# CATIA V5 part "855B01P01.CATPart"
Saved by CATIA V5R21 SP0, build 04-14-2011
Part number: 855B01P01
Bounding box of the stored display mesh (mm): x -76.5 to 76.5, y -25.54 to 25.54, z -56.557 to 6.5
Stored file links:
  C:\Users\ALI OZGUN\Desktop\alhan\855B01P01.CATPart
  Copy (1) of 845B01P21.CATPart
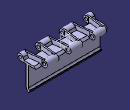
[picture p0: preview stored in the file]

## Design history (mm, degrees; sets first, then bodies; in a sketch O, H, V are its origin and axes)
Body1 (main body)
  Sketch1 on yz-plane, origin (0, 0, 0), H (0, 1, 0), V (0, 0, 1)
    construction line L1 (-19.05, 0) -> (19.05, 0)
    point P1 (-19.05, 0)
    point P2 (19.05, 0)
    line L2 (-19.05, 6.5) -> (19.05, 6.5)
    line L3 (19.05, -6.5) -> (-19.05, -6.5)
    arc A1 centre (19.05, 0) radius 6.5 from (19.05, 6.5) to (19.05, -6.5) cw
    arc A2 centre (-19.05, 0) radius 6.5 from (-19.05, -6.5) to (-19.05, 6.5) cw
    circle A3 centre (19.05, 0) radius 3.25
    circle A4 centre (-19.05, 0) radius 3.25
    distance L1 L2 = 6.5
    length L1 = 38.1
    distance P2 V = 19.05
    radius A3 = 3.25
    radius A4 = 3.25
    coincidence: P1 H
    horizontal: L1 H
    tangency: A1 L2, A2 L2, A1 L3, A2 L3
  Pad1: profile Sketch1, direction (1, 0, 0), length 76.5, mirrored extent
  Sketch2 on face of Pad1 from Sketch1.L2, origin (0, 0, 6.5), H (1, 0, 0), V (0, 1, 0)
    line L1 (38, -14) -> (64, -14)
    line L2 (64, -14) -> (64, -36.0786)
    line L3 (64, -36.0786) -> (38, -36.0786)
    line L4 (38, -36.0786) -> (38, -14)
    line L5 (-13, -14) -> (13, -14)
    line L6 (13, -14) -> (13, -36.0786)
    line L7 (13, -36.0786) -> (-13, -36.0786)
    line L8 (-13, -36.0786) -> (-13, -14)
    point P7 (13, -36.0786)
    line L9 (-64, -14) -> (-38, -14)
    line L10 (-38, -14) -> (-38, -32.269)
    line L11 (-38, -32.269) -> (-64, -32.269)
    line L12 (-64, -32.269) -> (-64, -14)
    line L13 (85.7823, 31.3847) -> (63.5, 31.3847)
    line L14 (63.5, 31.3847) -> (63.5, 14)
    line L15 (63.5, 14) -> (85.7823, 14)
    line L16 (85.7823, 14) -> (85.7823, 31.3847)
    point P17 (12.5, 31.3847)
    line L17 (12.5, 31.3847) -> (38.5, 31.3847)
    line L18 (38.5, 31.3847) -> (38.5, 14)
    line L19 (38.5, 14) -> (12.5, 14)
    line L20 (12.5, 14) -> (12.5, 31.3847)
    point P19 (38.5, 14)
    line L21 (-38.5, 32.0801) -> (-12.5, 32.0801)
    line L22 (-12.5, 32.0801) -> (-12.5, 14)
    line L23 (-12.5, 14) -> (-38.5, 14)
    line L24 (-38.5, 14) -> (-38.5, 32.0801)
    point P23 (-12.5, 14)
    line L25 (-81.4786, 33.8185) -> (-63.5, 33.8185)
    line L26 (-63.5, 33.8185) -> (-63.5, 14)
    line L27 (-63.5, 14) -> (-81.4786, 14)
    line L28 (-81.4786, 14) -> (-81.4786, 33.8185)
    point P27 (-63.5, 14)
    reference projected line E1 (76.5, 19.05) -> (76.5, -19.05) from edge [face of Pad1 from Sketch1.L2 | end face of Pad1]
    reference projected line E2 (-76.5, 19.05) -> (-76.5, -19.05) from edge [start face of Pad1 | face of Pad1 from Sketch1.L2]
    reference projected line E3 (-76.5, 19.05) -> (-76.5, -19.05) from edge [start face of Pad1 | face of Pad1 from Sketch1.L2]
    reference projected line E4 (76.5, 19.05) -> (76.5, -19.05) from edge [face of Pad1 from Sketch1.L2 | end face of Pad1]
    distance L14 E1 = 13
    distance L26 E2 = 13
    distance L12 E3 = 12.5
    distance L2 E4 = 12.5
    distance L23 L5 = 28
    distance L5 H = 14
    distance L4 L2 = 26
    distance L12 L10 = 26
    distance L10 L8 = 25
    distance L6 L4 = 25
    distance L24 L26 = 25
    distance L18 L14 = 25
    distance L26 L22 = 51
    distance L20 L18 = 26
    horizontal: L1 H, L3 H, L5 H, L7 H, L9 H, L11 H, L13 H, L15 H, L17 H, L19 H, L21 H, L23 H, L25 H, L27 H
    vertical: L2 V, L4 V, L6 V, L8 V, L10 V, L12 V, L14 V, L16 V, L18 V, L20 V, L22 V, L24 V, L26 V, L28 V
    coincidence: P7 L3, P17 L13, P19 L15, P23 L15, P27 L15, L1 L5, L9 L5
  Pocket1: profile Sketch2, direction (0, 0, -1), length 53.5
  Sketch3 on end face of Pad1, origin (76.5, 0, 0), H (0, 1, 0), V (0, 0, 1)
    projected arc E1 centre (19.05, 0) radius 6.5 from (19.05, -6.5) to (19.05, 6.5) ccw from edge [face of Pocket1 from Sketch2.L14 | face of Pad1 from Sketch1.A1]
    projected arc E2 centre (19.05, 0) radius 6.5 from (19.05, -6.5) to (13.0358, 2.4657) ccw from edge [face of Pocket1 from Sketch2.L14 | face of Pad1 from Sketch1.A1]
    point P1 (19.05, -6.5)
    projected arc E3 centre (-19.05, 0) radius 6.5 from (-19.05, 6.5) to (-19.05, -6.5) ccw from edge [face of Pad1 from Sketch1.A2 | end face of Pad1]
    projected arc E4 centre (-19.05, 0) radius 6.5 from (-13.0358, 2.4657) to (-19.05, -6.5) ccw from edge [face of Pad1 from Sketch1.A2 | end face of Pad1]
    point P4 (-19.05, -6.5)
    projected line E5 (-19.05, -6.5) -> (14, -6.5) from edge [face of Pad1 from Sketch1.L3 | end face of Pad1]
    point P5 (-19.05, -6.5)
    projected line E6 (19.05, -6.5) -> (14, -6.5) from edge [face of Pocket1 from Sketch2.L14 | face of Pad1 from Sketch1.L3]
    point P7 (19.05, -6.5)
    line L1 (-13.0358, 2.4657) -> (-11, -2.5)
    line L2 (-11, -2.5) -> (11, -2.5)
    point P10 (11, -2.5)
    line L3 (11, -2.5) -> (13.0358, 2.4657)
    distance L2 E5 = 4
    length L2 = 22
    distance P10 V = 11
    horizontal: L2 H
    tangency: L3 E1, L1 E3
    coincidence: P1 P7, P4 P5
  Pocket2: profile Sketch3, direction (-1, 0, 0), length 172.5, outer side
  Sketch4 on face of Pocket2 from Sketch3.L2, origin (0, 0, -2.5), H (1, 0, 0), V (0, 1, 0)
    projected line E1 (38, -14) -> (38, -25.55) from edge [face of Pocket2 | face of Pocket1 from Sketch2.L4]
    projected line E2 (38, -14) -> (38, -19.05) from edge [face of Pocket2 | face of Pocket1 from Sketch2.L4]
    point P1 (38, -14)
    point P2 (38, -25.55)
    projected line E3 (13, -25.55) -> (13, -14) from edge [face of Pocket2 | face of Pocket1 from Sketch2.L6]
    projected line E4 (13, -19.05) -> (13, -14) from edge [face of Pocket2 | face of Pocket1 from Sketch2.L6]
    point P3 (13, -25.55)
    point P4 (13, -14)
    projected line E5 (64, -25.55) -> (64, -14) from edge [face of Pocket2 | face of Pocket1 from Sketch2.L2]
    projected line E6 (64, -19.05) -> (64, -14) from edge [face of Pocket2 | face of Pocket1 from Sketch2.L2]
    point P5 (64, -25.55)
    point P6 (64, -14)
    projected line E7 (38.5, 14) -> (38.5, 25.55) from edge [face of Pocket2 | face of Pocket1 from Sketch2.L18]
    projected line E8 (38.5, 14) -> (38.5, 19.05) from edge [face of Pocket2 | face of Pocket1 from Sketch2.L18]
    point P7 (38.5, 14)
    point P8 (38.5, 25.55)
    projected line E9 (63.5, 14) -> (63.5, 25.55) from edge [face of Pocket1 from Sketch2.L14 | face of Pocket2]
    projected line E10 (63.5, 14) -> (63.5, 19.05) from edge [face of Pocket1 from Sketch2.L14 | face of Pocket2]
    point P9 (63.5, 14)
    point P10 (63.5, 25.55)
    projected line E11 (12.5, 25.55) -> (12.5, 14) from edge [face of Pocket2 | face of Pocket1 from Sketch2.L20]
    projected line E12 (12.5, 19.05) -> (12.5, 14) from edge [face of Pocket2 | face of Pocket1 from Sketch2.L20]
    point P11 (12.5, 25.55)
    point P12 (12.5, 14)
    offset line E13 (9.5, 25.55) -> (9.5, 14) from edge [face of Pocket2 | face of Pocket1 from Sketch2.L20]
    offset line E14 (9.5, 19.05) -> (9.5, 14) from edge [face of Pocket2 | face of Pocket1 from Sketch2.L20]
    point P13 (9.5, 25.55)
    point P14 (9.5, 14)
    offset line E15 (16, -25.55) -> (16, -14) from edge [face of Pocket2 | face of Pocket1 from Sketch2.L6]
    offset line E16 (16, -19.05) -> (16, -14) from edge [face of Pocket2 | face of Pocket1 from Sketch2.L6]
    point P15 (16, -25.55)
    point P16 (16, -14)
    offset line E17 (35, -14) -> (35, -25.55) from edge [face of Pocket2 | face of Pocket1 from Sketch2.L4]
    offset line E18 (35, -14) -> (35, -19.05) from edge [face of Pocket2 | face of Pocket1 from Sketch2.L4]
    point P17 (35, -14)
    point P18 (35, -25.55)
    offset line E19 (41.5, 14) -> (41.5, 25.55) from edge [face of Pocket2 | face of Pocket1 from Sketch2.L18]
    offset line E20 (41.5, 14) -> (41.5, 19.05) from edge [face of Pocket2 | face of Pocket1 from Sketch2.L18]
    point P19 (41.5, 14)
    point P20 (41.5, 25.55)
    offset line E21 (60.5, 14) -> (60.5, 25.55) from edge [face of Pocket1 from Sketch2.L14 | face of Pocket2]
    offset line E22 (60.5, 14) -> (60.5, 19.05) from edge [face of Pocket1 from Sketch2.L14 | face of Pocket2]
    point P21 (60.5, 14)
    point P22 (60.5, 25.55)
    offset line E23 (67, -25.55) -> (67, -14) from edge [face of Pocket2 | face of Pocket1 from Sketch2.L2]
    offset line E24 (67, -19.05) -> (67, -14) from edge [face of Pocket2 | face of Pocket1 from Sketch2.L2]
    point P23 (67, -25.55)
    point P24 (67, -14)
    line L1 (13, -14) -> (9.5, 14)
    line L2 (16, -14) -> (12.5, 14)
    line L3 (35, -14) -> (38.5, 14)
    line L4 (38, -14) -> (41.5, 14)
    line L5 (64, -14) -> (60.5, 14)
    line L6 (67, -14) -> (63.5, 14)
    projected line E25 through (0, -19.05) direction (1, 0) from axis of face of Pocket2
    projected line E26 (13, -19.05) -> (16, -19.05) from axis of face of Pocket2
    projected line E27 (64, -19.05) -> (67, -19.05) from axis of face of Pocket2
    projected line E28 (35, -19.05) -> (38, -19.05) from axis of face of Pocket2
    point P25 (-10000000, -19.05)
    point P26 (10000000, -19.05)
    point P27 (67, -19.05)
    point P28 (38, -19.05)
    point P29 (64, -19.05)
    point P30 (64, -19.05)
    point P31 (38, -19.05)
    point P32 (35, -19.05)
    point P33 (16, -19.05)
    point P34 (35, -19.05)
    point P35 (16, -19.05)
    point P36 (13, -19.05)
    point P37 (13, -19.05)
    projected line E29 through (0, 19.05) direction (1, 0) from axis of face of Pocket2
    projected line E30 (9.5, 19.05) -> (12.5, 19.05) from axis of face of Pocket2
    projected line E31 (38.5, 19.05) -> (41.5, 19.05) from axis of face of Pocket2
    projected line E32 (60.5, 19.05) -> (63.5, 19.05) from axis of face of Pocket2
    point P38 (-10000000, 19.05)
    point P39 (10000000, 19.05)
    point P40 (63.5, 19.05)
    point P41 (9.5, 19.05)
    point P42 (9.5, 19.05)
    point P43 (12.5, 19.05)
    point P44 (12.5, 19.05)
    point P45 (38.5, 19.05)
    point P46 (38.5, 19.05)
    point P47 (41.5, 19.05)
    point P48 (60.5, 19.05)
    point P49 (41.5, 19.05)
    point P50 (60.5, 19.05)
    point P51 (-10000000, -19.05)
    point P52 (10000000, -19.05)
    point P53 (-10000000, 19.05)
    point P54 (10000000, 19.05)
    construction line L7 through (0, -19.05) direction (-1, 0)
    construction line L8 through (0, 19.05) direction (-1, 0)
    point P55 (-10000000, -19.05)
    point P56 (10000000, -19.05)
    point P57 (-16, -19.05)
    point P58 (-13, -19.05)
    point P59 (-67, -19.05)
    point P60 (-64, -19.05)
    point P61 (-38, -19.05)
    point P62 (-35, -19.05)
    point P63 (-38, -25.55)
    point P64 (-38, -14)
    point P65 (-38, -19.05)
    point P66 (-13, -14)
    point P67 (-13, -25.55)
    point P68 (-13, -19.05)
    point P69 (-64, -14)
    point P70 (-64, -25.55)
    point P71 (-64, -19.05)
    point P72 (-38.5, 25.55)
    point P73 (-38.5, 14)
    point P74 (-38.5, 19.05)
    point P75 (-63.5, 25.55)
    point P76 (-63.5, 14)
    point P77 (-63.5, 19.05)
    point P78 (-12.5, 14)
    point P79 (-12.5, 25.55)
    point P80 (-12.5, 19.05)
    point P81 (-9.5, 14)
    point P82 (-9.5, 25.55)
    point P83 (-9.5, 19.05)
    point P84 (-16, -14)
    point P85 (-16, -25.55)
    point P86 (-16, -19.05)
    point P87 (-35, -25.55)
    point P88 (-35, -14)
    point P89 (-35, -19.05)
    point P90 (-41.5, 25.55)
    point P91 (-41.5, 14)
    point P92 (-41.5, 19.05)
    point P93 (-60.5, 25.55)
    point P94 (-60.5, 14)
    point P95 (-60.5, 19.05)
    point P96 (-67, -14)
    point P97 (-67, -25.55)
    line L9 (-13, -14) -> (-9.5, 14)
    line L10 (-16, -14) -> (-12.5, 14)
    line L11 (-35, -14) -> (-38.5, 14)
    line L12 (-38, -14) -> (-41.5, 14)
    line L13 (-64, -14) -> (-60.5, 14)
    line L14 (-67, -14) -> (-63.5, 14)
    point P98 (-10000000, 19.05)
    point P99 (10000000, 19.05)
    point P100 (-12.5, 19.05)
    point P101 (-9.5, 19.05)
    point P102 (-41.5, 19.05)
    point P103 (-38.5, 19.05)
    point P104 (-60.5, 19.05)
    construction line L15 through (0, -19.05) direction (-1, 0)
    line L16 (-13, -19.05) -> (-16, -19.05)
    line L17 (-64, -19.05) -> (-67, -19.05)
    line L18 (-35, -19.05) -> (-38, -19.05)
    construction line L19 (-38, -14) -> (-38, -25.55)
    line L20 (-38, -14) -> (-38, -19.05)
    construction line L21 (-13, -25.55) -> (-13, -14)
    line L22 (-13, -19.05) -> (-13, -14)
    construction line L23 (-64, -25.55) -> (-64, -14)
    line L24 (-64, -19.05) -> (-64, -14)
    construction line L25 (-38.5, 14) -> (-38.5, 25.55)
    line L26 (-38.5, 14) -> (-38.5, 19.05)
    construction line L27 (-63.5, 14) -> (-63.5, 25.55)
    line L28 (-63.5, 14) -> (-63.5, 19.05)
    construction line L29 (-12.5, 25.55) -> (-12.5, 14)
    line L30 (-12.5, 19.05) -> (-12.5, 14)
    construction line L31 (-9.5, 25.55) -> (-9.5, 14)
    line L32 (-9.5, 19.05) -> (-9.5, 14)
    construction line L33 (-16, -25.55) -> (-16, -14)
    line L34 (-16, -19.05) -> (-16, -14)
    construction line L35 (-35, -14) -> (-35, -25.55)
    line L36 (-35, -14) -> (-35, -19.05)
    construction line L37 (-41.5, 14) -> (-41.5, 25.55)
    line L38 (-41.5, 14) -> (-41.5, 19.05)
    construction line L39 (-60.5, 14) -> (-60.5, 25.55)
    line L40 (-60.5, 14) -> (-60.5, 19.05)
    construction line L41 (-67, -25.55) -> (-67, -14)
    line L42 (-67, -19.05) -> (-67, -14)
    construction line L43 through (0, 19.05) direction (-1, 0)
    line L44 (-9.5, 19.05) -> (-12.5, 19.05)
    line L45 (-38.5, 19.05) -> (-41.5, 19.05)
    line L46 (-60.5, 19.05) -> (-63.5, 19.05)
    parallelism: L2 L1, L4 L3
    coincidence: E1 P28, E5 P29, E25 P30, E25 P31, E25 P32, E15 P33, E17 P34, E25 P35, E25 P36, E3 P37, E13 P41, E29 P42, E29 P43, E11 P44, E7 P45, E29 P46, E29 P47, E29 P48, E19 P49, E21 P50, P28 P31, P29 P30, P32 P34, P33 P35, P36 P37, P41 P42, P43 P44, P45 P46, P47 P49, P48 P50
    symmetry: P26 P51 V, P25 P52 V, E25 L7 V, P39 P53 V, P38 P54 V, E29 L8 V, P26 P55 V, P25 P56 V, P33 P57 V, P37 P58 V, P27 P59 V, P29 P60 V, P28 P61 V, P34 P62 V, E25 L15 V, P2 P63 V, P1 P64 V, P31 P65 V, E1 L19 V, P4 P66 V, P3 P67 V, P36 P68 V, E3 L21 V, P6 P69 V, P5 P70 V, P30 P71 V, E5 L23 V, P8 P72 V, P7 P73 V, P46 P74 V, E7 L25 V, P10 P75 V, P9 P76 V, P40 P77 V, E9 L27 V, P12 P78 V, P11 P79 V, P43 P80 V, E11 L29 V, P14 P81 V, P13 P82 V, P42 P83 V, E13 L31 V, P16 P84 V, P15 P85 V, P35 P86 V, E15 L33 V, P18 P87 V, P17 P88 V, P32 P89 V, E17 L35 V, P20 P90 V, P19 P91 V, P47 P92 V, E19 L37 V, P22 P93 V, P21 P94 V, P48 P95 V, E21 L39 V, P24 P96 V, P23 P97 V, E23 L41 V, L1 L9 V, L2 L10 V, L3 L11 V, L4 L12 V, L5 L13 V, L6 L14 V, P39 P98 V, P38 P99 V, P44 P100 V, P41 P101 V, P49 P102 V, P45 P103 V, P50 P104 V, E29 L43 V, E25 L18 V, E25 L17 V, E25 L16 V, E1 L20 V, E3 L22 V, E5 L24 V, E7 L26 V, E9 L28 V, E11 L30 V, E13 L32 V, E15 L34 V, E17 L36 V, E19 L38 V, E21 L40 V, E23 L42 V, E29 L46 V, E29 L45 V, E29 L44 V
  Pad2: profile Sketch4, direction (0, 0, 1), length 9
  Sketch5 on yz-plane, origin (0, 0, 0), H (0, 1, 0), V (0, 0, 1)
    projected circle E1 centre (-19.05, 0) radius 3.25 from edge [end face of Pad1 | face of Pad1 from Sketch1.A4]
    circle A1 centre (19.05, 0) radius 3.25
    reference projected circle E2 centre (19.05, 0) radius 3.25 from edge [face of Pad1 from Sketch1.A3 | face of Pad2]
    coincidence: A1 E2
  Pocket3: profile Sketch5, direction (-1, 0, 0), length 95, mirrored extent
  RemoveFace1: RemoveFaces (face of Pocket2 from Sketch3.L3; face of Pocket2; face of Pocket2 from Sketch3.L3; face of Pocket2; face of Pocket2 from Sketch3.L1; face of Pocket2; face of Pocket2 from Sketch3.L1; face of Pocket2; face of Pocket2; face of Pocket2; face of Pocket2; face of Pocket2 from Sketch3.L3; face of Pocket2 from Sketch3.L3; face of Pocket2 from Sketch3.L1)
  Chamfer1: length 4, angle 45, on edge [face of Pocket1 from Sketch2.L27 | face of Pocket2 from Sketch3.L2]; edge [face of Pocket1 from Sketch2.L9 | face of Pocket2 from Sketch3.L2]; edge [face of Pocket1 from Sketch2.L19 | face of Pocket2 from Sketch3.L2]; edge [face of Pocket1 from Sketch2.L5 | face of Pocket2 from Sketch3.L2]; edge [face of Pocket1 from Sketch2.L1 | face of Pocket2 from Sketch3.L2]; edge [face of Pocket1 from Sketch2.L15 | face of Pocket2 from Sketch3.L2]; edge [face of Pocket1 from Sketch2.L23 | face of Pocket2 from Sketch3.L2]
  Sketch6 on yz-plane, origin (0, 0, 0), H (0, 1, 0), V (0, 0, 1)
    point P1 (-4.05, -6.5)
    line L1 (-4.05, -6.5) -> (-4.05, -47.8504)
    arc A1 centre (2.9349, -47.8504) radius 6.9849 from (-4.05, -47.8504) to (0.7968, -54.5) ccw
    point P4 (0.7968, -54.5)
    reference projected point E1 (-19.05, 0) from axis of face of Pocket2
    reference intersected line E2 (19.05, -6.5) -> (-19.05, -6.5) from face of Pocket2
    reference projected line E3 (-19.05, -6.5) -> (19.05, -6.5) from edge [face of Pocket2 | end face of Pad1]
    distance L1 E1 = 15
    distance P4 E2 = 48
    vertical: L1 V
    tangency: A1 L1
    coincidence: P1 E3
  Pad3: profile Sketch6, direction (1, 0, 0), up to end face of Pad1, opposite side up to start face of Pad1, thin wall 5
  Fillet1: radius 1, on edge [face of Pad3 | face of Pad3] (x2)
Body2
  Solid1: linked copy from another document
  Translate1: Direction zx-plane, Length 38.1, ToTransfor Solid1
